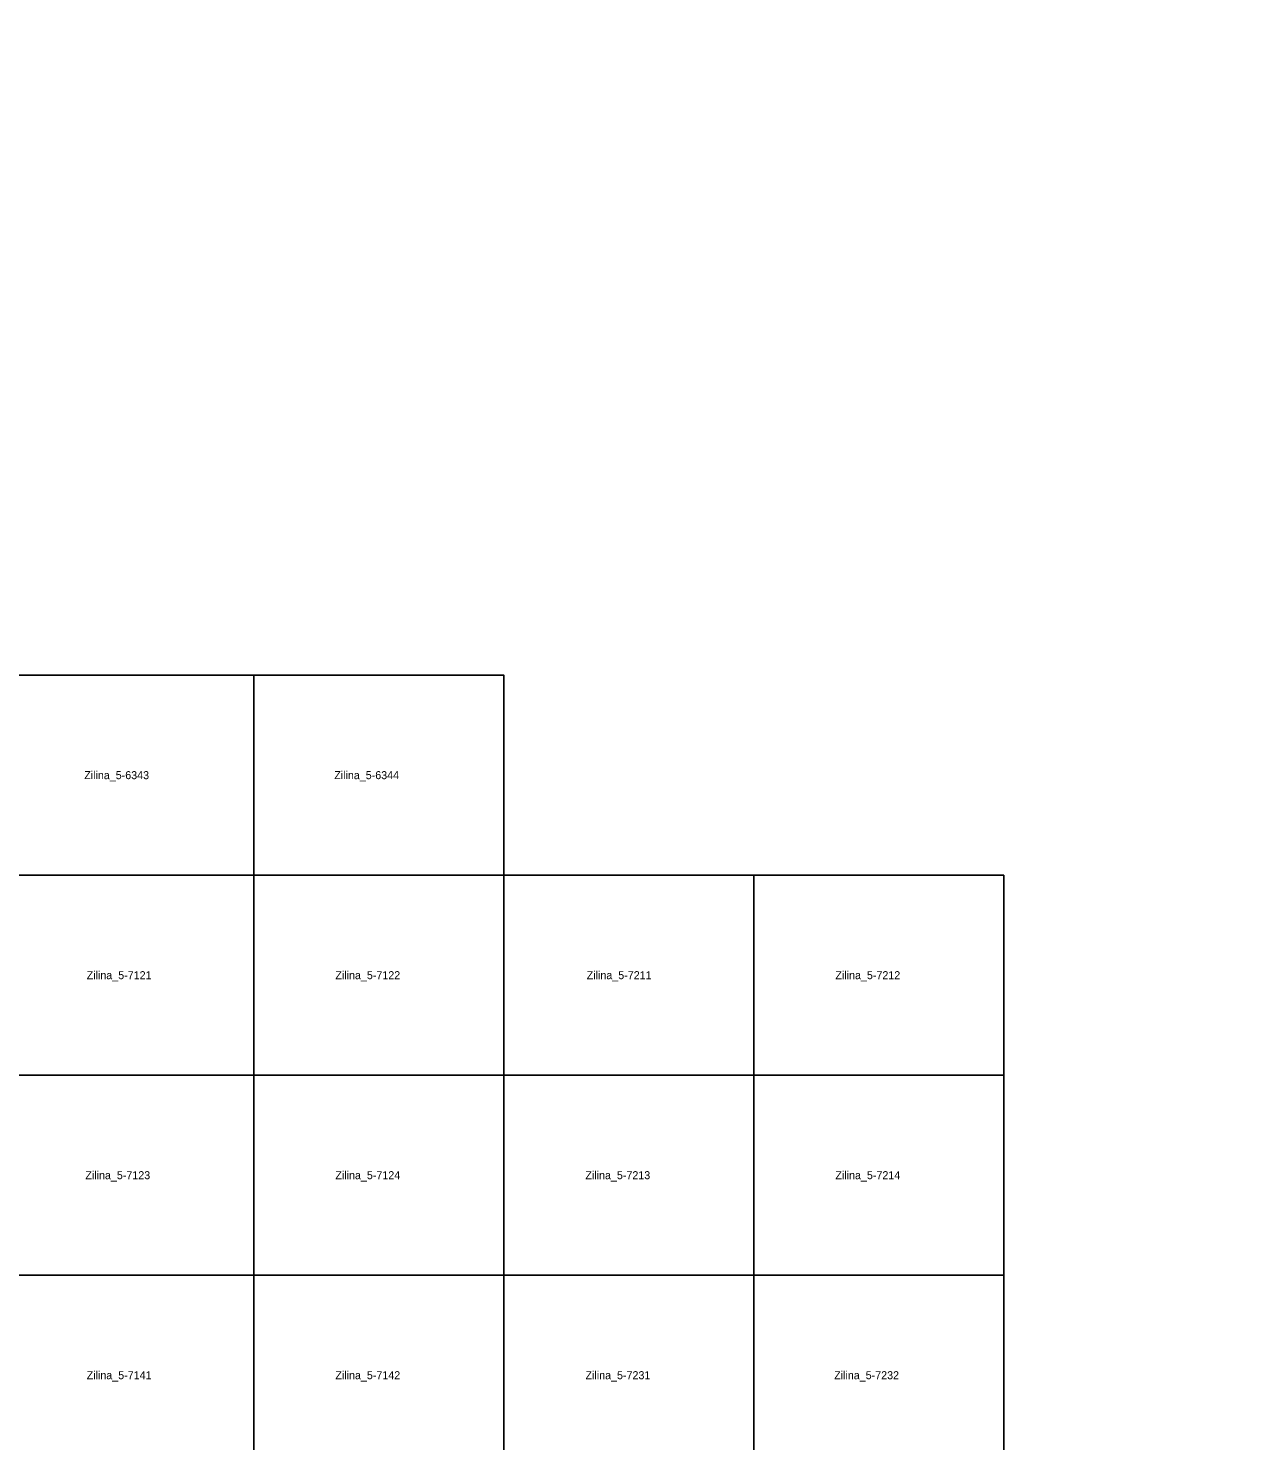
# Model space of a CAD drawing. Extents: x -445938 to -437812, y -1177250 to -1169500.
# Drawn here: x -439344 to -437812, y -1174707 to -1172941 of the extents above; entities that cross this region are included whole.
import ezdxf

# ---------------------------------------------------------------- set-up
doc = ezdxf.new("R2010")
doc.units = 0
for name, color, linetype in [('Vrstva 1', 7, 'Continuous'), ('Vrstva 4', 7, 'Continuous'), ('Vrstva 6', 7, 'Continuous')]:
    doc.layers.add(name, color=color, linetype=linetype)

msp = doc.modelspace()

# ---------------------------------------------------------------- linework, layer by layer
at = {"layer": 'Vrstva 1'}
msp.add_lwpolyline([(-440937.5, -1172000), (-440625, -1172000), (-440625, -1173000), (-440000, -1173000), (-440000, -1173500), (-439375, -1173500), (-439375, -1173750), (-438750, -1173750), (-438750, -1174000), (-438125, -1174000), (-438125, -1174750), (-437812.5, -1174750), (-437812.5, -1176750), (-438125, -1176750), (-438125, -1177000), (-438437.5, -1177000), (-438437.5, -1177250), (-439687.5, -1177250), (-439687.5, -1176750), (-440625, -1176750), (-440625, -1175500), (-441562.5, -1175500)], dxfattribs=at)
at = {"layer": 'Vrstva 4'}
for points in [[(-439062.5, -1173750), (-439062.5, -1174000), (-439375, -1174000), (-439375, -1173750)], [(-438750, -1173750), (-438750, -1174000), (-439062.5, -1174000), (-439062.5, -1173750)], [(-439062.5, -1174000), (-439062.5, -1174250), (-439375, -1174250), (-439375, -1174000)], [(-438750, -1174000), (-438750, -1174250), (-439062.5, -1174250), (-439062.5, -1174000)], [(-438437.5, -1174000), (-438437.5, -1174250), (-438750, -1174250), (-438750, -1174000)], [(-438125, -1174000), (-438125, -1174250), (-438437.5, -1174250), (-438437.5, -1174000)], [(-439062.5, -1174250), (-439062.5, -1174500), (-439375, -1174500), (-439375, -1174250)], [(-438750, -1174250), (-438750, -1174500), (-439062.5, -1174500), (-439062.5, -1174250)], [(-438437.5, -1174250), (-438437.5, -1174500), (-438750, -1174500), (-438750, -1174250)], [(-438125, -1174250), (-438125, -1174500), (-438437.5, -1174500), (-438437.5, -1174250)], [(-439062.5, -1174500), (-439062.5, -1174750), (-439375, -1174750), (-439375, -1174500)], [(-438750, -1174500), (-438750, -1174750), (-439062.5, -1174750), (-439062.5, -1174500)], [(-438437.5, -1174500), (-438437.5, -1174750), (-438750, -1174750), (-438750, -1174500)], [(-438125, -1174500), (-438125, -1174750), (-438437.5, -1174750), (-438437.5, -1174500)]]:
    msp.add_lwpolyline(points, close=True, dxfattribs=at)

# ---------------------------------------------------------------- texts
at = {"layer": 'Vrstva 6'}
for s, p in [('Zilina_5-6343', (-439274.296, -1173880)), ('Zilina_5-6344', (-438961.796, -1173880)), ('Zilina_5-7121', (-439271.186, -1174130)), ('Zilina_5-7122', (-438960.379, -1174130)), ('Zilina_5-7211', (-438646.186, -1174130)), ('Zilina_5-7212', (-438335.379, -1174130)), ('Zilina_5-7123', (-439272.879, -1174380)), ('Zilina_5-7124', (-438960.379, -1174380)), ('Zilina_5-7213', (-438647.879, -1174380)), ('Zilina_5-7214', (-438335.379, -1174380)), ('Zilina_5-7141', (-439271.186, -1174630)), ('Zilina_5-7142', (-438960.379, -1174630)), ('Zilina_5-7231', (-438647.721, -1174630)), ('Zilina_5-7232', (-438336.914, -1174630))]:
    msp.add_text(s, height=10, dxfattribs=at).set_placement(p)

doc.saveas('drawing.dxf')
